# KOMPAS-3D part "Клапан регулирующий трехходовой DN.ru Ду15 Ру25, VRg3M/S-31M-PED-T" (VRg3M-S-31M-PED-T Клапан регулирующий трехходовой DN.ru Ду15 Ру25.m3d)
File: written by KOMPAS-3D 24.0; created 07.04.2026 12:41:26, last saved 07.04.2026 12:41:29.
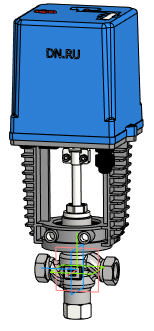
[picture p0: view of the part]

Document properties: Автор: DN.RU; Полное имя файла: D:\PROJECT CAD\DN.RU\...197\DN15\VRg3M-S-31M-PED-T Клапан регулирующий трехходовой DN.ru Ду15 Ру25.m3d

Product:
- Body: Твердое тело1  | qty 1
    Масса: 18.937726
- Part/product: Клапан регулирующий трехходовой DN.ru Ду15 Ру25  | designation VRg3M/S-31M-PED-T
    Масса: 3.1
    Раздел спецификации: Прочие изделия
    Комментарий: D230-11263
    Примечание: D230-11263
    additional columns: Типовые

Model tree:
1. Твердое тело1  (labels: Твердое тело1)

Expressions: VRg3M/S-31M-PED-T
